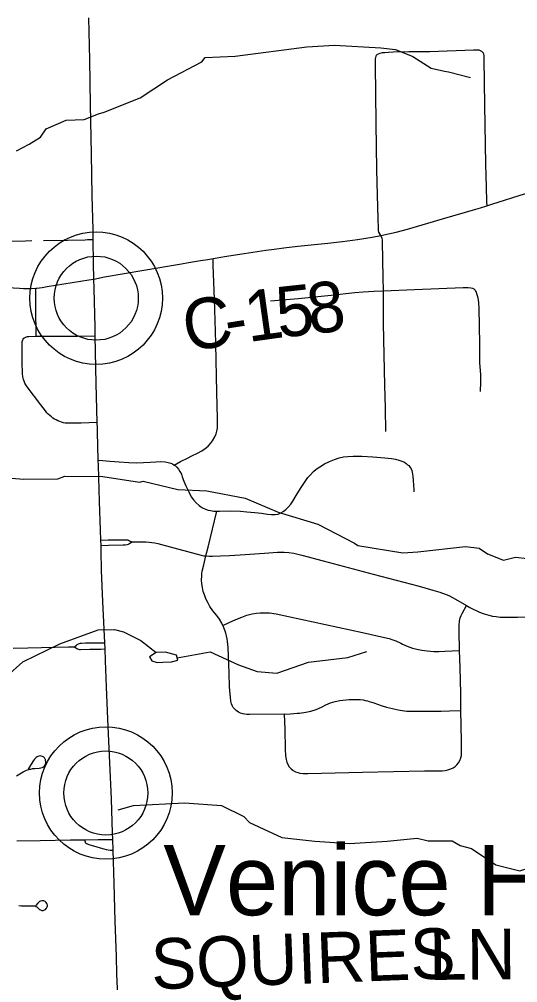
# Model space of a CAD drawing. Extents: x -6.4 to 34, y -4.2 to 22.
# Drawn here: x 5.367 to 5.927, y 19.085 to 20.167 of the extents above; entities that cross this region are included whole.
import ezdxf

# ---------------------------------------------------------------- set-up
doc = ezdxf.new("R2010")
doc.units = 0
for name, color, linetype in [('GM_X_County_Road', 7, 'Continuous'), ('GM_X_County_Road_Text', 7, 'Continuous'), ('GM_X_Minor_Lake', 7, 'Continuous'), ('GM_X_Minor_River', 7, 'Continuous'), ('GM_X_State_Route', 7, 'Continuous'), ('GM_X_Township_Road', 7, 'Continuous'), ('GM_X_Unincorporated', 7, 'Continuous'), ('GM_X_Unincorporated_Location', 7, 'Continuous'), ('GM_X_Unincorporated_Text', 7, 'Continuous')]:
    doc.layers.add(name, color=color, linetype=linetype)

msp = doc.modelspace()

# ---------------------------------------------------------------- linework, layer by layer
at = {"layer": 'GM_X_County_Road'}
msp.add_lwpolyline([(5.4509, 19.875), (5.4626, 19.8774), (5.5068, 19.8848), (5.5493, 19.8921), (5.5572, 19.8935), (5.5706, 19.8957), (5.5787, 19.897), (5.5847, 19.898), (5.5894, 19.8987), (5.5976, 19.9001), (5.6196, 19.9036), (5.6439, 19.9074), (5.6533, 19.9087), (5.6641, 19.9101), (5.6797, 19.912), (5.7134, 19.9153), (5.7302, 19.9173), (5.7468, 19.9193), (5.7633, 19.9221), (5.7731, 19.9239), (5.7816, 19.9257), (5.7902, 19.9277), (5.803, 19.9309), (5.8425, 19.9427), (5.8799, 19.9535), (5.8851, 19.955), (5.892, 19.9572), (5.8979, 19.959), (5.9357, 19.9709)], dxfattribs=at)
at = {"layer": 'GM_X_Minor_Lake'}
msp.add_line((5.5219, 19.4445), (5.5283, 19.4446), dxfattribs=at)
msp.add_lwpolyline([(5.5283, 19.4446), (5.5381, 19.4451), (5.5449, 19.4471), (5.5437, 19.4528), (5.5312, 19.456), (5.5206, 19.4555), (5.5134, 19.4508), (5.5158, 19.4463), (5.5219, 19.4445)], dxfattribs=at)
at = {"layer": 'GM_X_Minor_River'}
for points in [[(5.3637, 20.019), (5.378, 20.0265), (5.3907, 20.0343), (5.397, 20.0435), (5.4196, 20.0534), (5.44, 20.0541), (5.4558, 20.0604), (5.4623, 20.0624), (5.5029, 20.0783), (5.5333, 20.0985), (5.5719, 20.1189), (5.5756, 20.1236), (5.6093, 20.1253), (5.6898, 20.1357), (5.7212, 20.1374), (5.7732, 20.1345), (5.7895, 20.1328), (5.8089, 20.1248), (5.8296, 20.1119), (5.8448, 20.1083), (5.849, 20.1076), (5.8737, 20.1012)], [(5.3204, 19.6545), (5.372, 19.6501), (5.4102, 19.6507), (5.4181, 19.6535), (5.4609, 19.6534), (5.5019, 19.6469), (5.5061, 19.6481), (5.5452, 19.6385), (5.5778, 19.6372), (5.6208, 19.6288), (5.6578, 19.6131), (5.7023, 19.5998), (5.7435, 19.5784), (5.7474, 19.5758), (5.7979, 19.5676), (5.8145, 19.5686), (5.8682, 19.5748), (5.8834, 19.5728), (5.893, 19.5665), (5.9109, 19.5592), (5.9245, 19.5625), (5.9374, 19.5612)], [(5.2874, 19.3555), (5.2836, 19.3558), (5.2943, 19.3742), (5.3391, 19.411), (5.3528, 19.4287), (5.3711, 19.445), (5.4125, 19.4654), (5.4554, 19.481), (5.4739, 19.4816), (5.4842, 19.4788), (5.5037, 19.4692), (5.5206, 19.4555)], [(5.5444, 19.4497), (5.5815, 19.4565), (5.6132, 19.4418), (5.6341, 19.4342), (5.6561, 19.4323), (5.6919, 19.4447), (5.7362, 19.45), (5.7573, 19.4568)], [(5.478, 19.2789), (5.4953, 19.2838), (5.5524, 19.287), (5.5942, 19.2839), (5.6194, 19.2714), (5.6255, 19.2647), (5.6618, 19.2478), (5.699, 19.2439), (5.738, 19.2411), (5.7804, 19.2437), (5.814, 19.2473), (5.8262, 19.2441), (5.8531, 19.2442), (5.8623, 19.239), (5.8748, 19.2355), (5.9024, 19.2173), (5.9294, 19.2105), (5.9347, 19.2125), (5.9385, 19.2103), (5.9977, 19.2242), (6.0072, 19.2232), (6.0509, 19.2122)]]:
    msp.add_lwpolyline(points, dxfattribs=at)
at = {"layer": 'GM_X_State_Route'}
for points in [[(5.4547, 19.7077), (5.4545, 19.7139), (5.4534, 19.7577), (5.4523, 19.8113), (5.4521, 19.8208), (5.4512, 19.8645), (5.4509, 19.875), (5.4504, 19.8924), (5.45, 19.9193), (5.4498, 19.9305), (5.4489, 19.9683), (5.4481, 20.0156), (5.4471, 20.0706), (5.4462, 20.1213), (5.4452, 20.1683)], [(5.478, 19.0616), (5.4767, 19.0949), (5.4762, 19.1142), (5.4747, 19.1538), (5.4735, 19.1962), (5.4724, 19.2335), (5.472, 19.2458), (5.4718, 19.2527), (5.4704, 19.2914), (5.4687, 19.3316), (5.4666, 19.3806), (5.4651, 19.4172), (5.464, 19.4464), (5.4634, 19.4596), (5.4631, 19.4665), (5.4624, 19.4818), (5.4609, 19.513), (5.4595, 19.5476), (5.4591, 19.57), (5.4589, 19.5757), (5.4587, 19.5819), (5.4583, 19.5931), (5.4572, 19.6253), (5.4559, 19.6657), (5.4557, 19.6715), (5.4548, 19.7035), (5.4547, 19.7077)]]:
    msp.add_lwpolyline(points, dxfattribs=at)
at = {"layer": 'GM_X_Township_Road'}
for points in [[(5.7731, 19.9239), (5.7708, 19.9275), (5.7705, 19.9295), (5.7705, 19.9316), (5.77, 19.9431), (5.7693, 19.9693), (5.7686, 19.9981), (5.7679, 20.0495), (5.7675, 20.0837), (5.7672, 20.1147), (5.7671, 20.1205), (5.7672, 20.1223), (5.7674, 20.1239), (5.7678, 20.1254), (5.7683, 20.1263), (5.769, 20.127), (5.7705, 20.128), (5.7725, 20.1287), (5.7748, 20.1292), (5.7776, 20.1295), (5.7817, 20.1299), (5.787, 20.1302), (5.8045, 20.1306), (5.8281, 20.1306), (5.8772, 20.1323), (5.8809, 20.1324), (5.8832, 20.1322), (5.8848, 20.1317), (5.8863, 20.131), (5.887, 20.1302), (5.888, 20.1289), (5.8885, 20.1275), (5.8887, 20.1258), (5.8889, 20.122), (5.8896, 20.0701), (5.8905, 20.0041), (5.8913, 19.9783), (5.8919, 19.9621), (5.892, 19.9572)], [(5.3088, 19.877), (5.3104, 19.8826), (5.3134, 19.8926), (5.3158, 19.9003), (5.3175, 19.905), (5.3186, 19.9074), (5.3198, 19.9092), (5.3208, 19.9103), (5.3232, 19.9123), (5.3263, 19.9144), (5.3296, 19.916), (5.3317, 19.9167), (5.3339, 19.9172), (5.3361, 19.9174), (5.3389, 19.9174), (5.374, 19.918), (5.381, 19.9181)], [(5.3943, 19.9184), (5.4213, 19.9188), (5.4411, 19.9191), (5.4436, 19.9192), (5.45, 19.9193)], [(5.7786, 19.7039), (5.7783, 19.73), (5.7777, 19.7557), (5.7767, 19.7899), (5.7762, 19.8251), (5.7761, 19.8617), (5.7759, 19.8766), (5.7751, 19.9169), (5.775, 19.9191), (5.7747, 19.9206), (5.7731, 19.9239)], [(5.5411, 19.6661), (5.5482, 19.67), (5.5558, 19.674), (5.5608, 19.6764), (5.567, 19.6793), (5.5719, 19.6821), (5.5756, 19.6846), (5.579, 19.6875), (5.5817, 19.6902), (5.5839, 19.6933), (5.5865, 19.6977), (5.588, 19.7012), (5.5889, 19.7043), (5.5895, 19.7075), (5.5896, 19.7119), (5.5895, 19.7184), (5.5888, 19.7474), (5.5876, 19.8021), (5.5873, 19.8164), (5.5862, 19.8525), (5.5849, 19.8904), (5.5847, 19.898)], [(5.3088, 19.877), (5.3156, 19.8753), (5.3237, 19.8729), (5.3303, 19.8709), (5.338, 19.8689), (5.3483, 19.8667), (5.3605, 19.865), (5.3673, 19.8646), (5.3716, 19.8645), (5.3759, 19.8644), (5.3803, 19.8645), (5.3854, 19.8648), (5.3867, 19.8649), (5.3925, 19.8655), (5.3983, 19.8665), (5.445, 19.874), (5.4509, 19.875)], [(5.3858, 19.8107), (5.3854, 19.8424), (5.3854, 19.8605), (5.3854, 19.8648)], [(5.6493, 19.8506), (5.6803, 19.8531), (5.7174, 19.8569), (5.7438, 19.8597), (5.7532, 19.8606), (5.7651, 19.8613), (5.7761, 19.8617), (5.8111, 19.8632), (5.8655, 19.8656), (5.8711, 19.8656)], [(5.8711, 19.8656), (5.8742, 19.8652), (5.876, 19.8647), (5.8774, 19.864), (5.8782, 19.8632), (5.8789, 19.8623), (5.8795, 19.8615), (5.8801, 19.8602), (5.8807, 19.8587), (5.8815, 19.8564), (5.882, 19.854), (5.8824, 19.8515), (5.8828, 19.8482), (5.8832, 19.8423), (5.8837, 19.8224), (5.8839, 19.8019), (5.8838, 19.7948), (5.8841, 19.7812), (5.8849, 19.7673), (5.8849, 19.7596), (5.8846, 19.7487)], [(5.4545, 19.7139), (5.4364, 19.7133), (5.4239, 19.713), (5.4213, 19.7131), (5.4187, 19.7133), (5.4165, 19.7137), (5.4144, 19.7143), (5.4124, 19.7149), (5.4103, 19.7157), (5.4084, 19.7167), (5.4065, 19.7178), (5.4047, 19.7189), (5.4031, 19.7202), (5.4014, 19.7217), (5.3996, 19.7233), (5.398, 19.7249), (5.3963, 19.727), (5.3912, 19.7338), (5.3758, 19.7541), (5.3744, 19.7562), (5.3733, 19.7582), (5.3724, 19.7602), (5.3718, 19.7621), (5.3713, 19.7638), (5.371, 19.7656), (5.3707, 19.7686), (5.3704, 19.782), (5.3701, 19.7972), (5.3701, 19.8003), (5.3702, 19.8027), (5.3704, 19.8043), (5.3706, 19.8056), (5.371, 19.8067), (5.3715, 19.8076), (5.3721, 19.8084), (5.3728, 19.8091), (5.3739, 19.8098), (5.3751, 19.8102), (5.3763, 19.8104), (5.3776, 19.8105), (5.3858, 19.8107), (5.4324, 19.811), (5.4523, 19.8113)], [(5.4557, 19.6715), (5.4606, 19.6711), (5.4687, 19.6704), (5.4793, 19.6696), (5.4901, 19.6689), (5.4989, 19.6685), (5.5064, 19.6689), (5.5139, 19.6695), (5.5203, 19.6699), (5.5258, 19.67), (5.5307, 19.6698), (5.5342, 19.6691), (5.5371, 19.6683), (5.5392, 19.6673), (5.5411, 19.6661), (5.5423, 19.6653), (5.5439, 19.6637), (5.5459, 19.6614), (5.5475, 19.6589), (5.5491, 19.6557), (5.5501, 19.6529), (5.5518, 19.6482), (5.5539, 19.6429), (5.5573, 19.636), (5.5602, 19.6306), (5.5628, 19.6269), (5.5658, 19.6236), (5.5692, 19.6207), (5.5707, 19.6195), (5.5728, 19.6181), (5.5763, 19.6164), (5.5793, 19.6154), (5.5819, 19.6149), (5.5857, 19.6145), (5.5889, 19.6145), (5.592, 19.6145), (5.6044, 19.6148), (5.6156, 19.6144), (5.6225, 19.6137), (5.6317, 19.6127), (5.6391, 19.6119), (5.6459, 19.611), (5.6504, 19.6106), (5.6545, 19.6106), (5.6576, 19.6111), (5.6606, 19.6123), (5.6634, 19.6139), (5.6665, 19.6162), (5.6692, 19.6188), (5.6721, 19.6223), (5.6742, 19.6254), (5.678, 19.6319), (5.6827, 19.6399), (5.6872, 19.6466), (5.6912, 19.652), (5.6936, 19.6548), (5.6974, 19.6587), (5.7006, 19.6614), (5.7046, 19.6642), (5.7099, 19.6673), (5.7154, 19.67), (5.721, 19.6724), (5.7263, 19.6741), (5.731, 19.6752), (5.7359, 19.6758), (5.742, 19.6761), (5.7519, 19.676), (5.7643, 19.6753), (5.7776, 19.6742), (5.7851, 19.6734), (5.7894, 19.6727), (5.7932, 19.6717), (5.7967, 19.6706), (5.7997, 19.6693), (5.8016, 19.6677), (5.8031, 19.6665), (5.8044, 19.6655), (5.8052, 19.6645), (5.8061, 19.6634), (5.807, 19.6618), (5.8078, 19.6601), (5.8084, 19.658), (5.8091, 19.6536), (5.8095, 19.6487), (5.8102, 19.6383), (5.8103, 19.6359)], [(5.6645, 19.3865), (5.6254, 19.386), (5.6226, 19.386), (5.618, 19.3866), (5.6155, 19.3874), (5.6132, 19.3886), (5.6106, 19.3904), (5.6087, 19.3922), (5.6074, 19.3938), (5.6064, 19.3955), (5.6054, 19.3979), (5.6047, 19.4011), (5.6042, 19.4055), (5.6037, 19.4089), (5.6031, 19.4172), (5.6027, 19.4329), (5.6015, 19.4612), (5.6009, 19.4679), (5.6005, 19.4709), (5.5998, 19.4745), (5.599, 19.4772), (5.5983, 19.4797), (5.5965, 19.4843), (5.5957, 19.4859), (5.5944, 19.4887), (5.5919, 19.4929), (5.5888, 19.4972), (5.5865, 19.4999), (5.5843, 19.5026), (5.5811, 19.5073), (5.5786, 19.5117), (5.5766, 19.5158), (5.5749, 19.5202), (5.5737, 19.5243), (5.5726, 19.5286), (5.5721, 19.5326), (5.5718, 19.5371), (5.5719, 19.5413), (5.572, 19.5441), (5.5725, 19.5469), (5.5741, 19.5541), (5.5766, 19.564), (5.5793, 19.574), (5.5889, 19.6145)], [(5.4587, 19.5819), (5.4668, 19.5821), (5.4775, 19.5822), (5.4853, 19.5823), (5.4869, 19.5822), (5.4884, 19.582), (5.4897, 19.5816)], [(5.4897, 19.5816), (5.4909, 19.5811), (5.4934, 19.5799)], [(5.4589, 19.5757), (5.4672, 19.576), (5.4837, 19.5765), (5.486, 19.5766), (5.4883, 19.5769), (5.4895, 19.5772), (5.4902, 19.5775)], [(5.4902, 19.5775), (5.4909, 19.5779), (5.4934, 19.5799)], [(5.4934, 19.5799), (5.5035, 19.5799), (5.5065, 19.5799), (5.5096, 19.5798), (5.5127, 19.5796), (5.5157, 19.5792), (5.5191, 19.5786), (5.5225, 19.578), (5.5405, 19.5733), (5.5712, 19.565), (5.5743, 19.5643), (5.5766, 19.564), (5.5803, 19.5638), (5.584, 19.5637), (5.5931, 19.564), (5.6032, 19.5645), (5.615, 19.5654), (5.6423, 19.5673), (5.6572, 19.5683), (5.6647, 19.5684), (5.6697, 19.5681), (5.6753, 19.5672), (5.6844, 19.565), (5.7085, 19.5587), (5.7646, 19.5437), (5.8162, 19.5301), (5.8317, 19.5257), (5.8395, 19.5234), (5.8465, 19.5207), (5.8494, 19.5195), (5.8545, 19.517), (5.8692, 19.5083), (5.8732, 19.5062), (5.8838, 19.5011), (5.889, 19.4991), (5.8944, 19.4974), (5.8986, 19.4965), (5.9026, 19.4959), (5.9072, 19.4954), (5.912, 19.4952), (5.9268, 19.4954), (5.9604, 19.4958)], [(5.6645, 19.3865), (5.6651, 19.3694), (5.6657, 19.347), (5.6661, 19.3396), (5.6667, 19.3354), (5.6674, 19.3325), (5.6686, 19.3298), (5.6702, 19.3273), (5.6722, 19.3251), (5.6745, 19.3233), (5.6771, 19.3218), (5.6799, 19.3207), (5.6821, 19.3202), (5.6857, 19.3198), (5.6912, 19.3198), (5.7527, 19.3211), (5.822, 19.3226), (5.8326, 19.3227), (5.8369, 19.3228), (5.8419, 19.3229), (5.8455, 19.3231), (5.8484, 19.3237), (5.8518, 19.3249), (5.8545, 19.3262), (5.8565, 19.3275), (5.8586, 19.3295), (5.8604, 19.3318), (5.8619, 19.3344), (5.8629, 19.3372), (5.8636, 19.3401), (5.8639, 19.3437), (5.8639, 19.3455), (5.8637, 19.3566), (5.8631, 19.3906), (5.8628, 19.4096), (5.8622, 19.4388), (5.8616, 19.458), (5.8611, 19.4801), (5.861, 19.4863), (5.8615, 19.4908), (5.8623, 19.4945), (5.8634, 19.4973), (5.8645, 19.4996), (5.8692, 19.5083)], [(5.5957, 19.4859), (5.6028, 19.4892), (5.6101, 19.4926), (5.6169, 19.4954), (5.6227, 19.4974), (5.6287, 19.4989), (5.6335, 19.4997), (5.6377, 19.5001), (5.6432, 19.5003), (5.6481, 19.5001), (5.6554, 19.4991), (5.7526, 19.4781), (5.7774, 19.4726), (5.7823, 19.4714), (5.7865, 19.47), (5.7899, 19.4688), (5.7954, 19.4662), (5.7976, 19.4651), (5.8028, 19.4627), (5.8086, 19.4606), (5.8135, 19.4594), (5.819, 19.4584), (5.8252, 19.4575), (5.8327, 19.4569), (5.8383, 19.4569), (5.8451, 19.4572), (5.8532, 19.4576), (5.8616, 19.458)], [(5.4291, 19.462), (5.4311, 19.464), (5.432, 19.4646), (5.4326, 19.4649), (5.4336, 19.4654), (5.4346, 19.4657), (5.4358, 19.466), (5.437, 19.4661), (5.4414, 19.4663), (5.4457, 19.4664), (5.4581, 19.4665), (5.4631, 19.4665)], [(5.3602, 19.4606), (5.3765, 19.4608), (5.4222, 19.4619)], [(5.4222, 19.4619), (5.4291, 19.462), (5.4305, 19.4608), (5.4315, 19.4601), (5.4325, 19.4596), (5.4335, 19.4593), (5.4346, 19.4591), (5.4358, 19.459), (5.4461, 19.4593), (5.4587, 19.4595), (5.4634, 19.4596)], [(5.6645, 19.3865), (5.6715, 19.3869), (5.6792, 19.3874), (5.6816, 19.3876), (5.6889, 19.3886), (5.6944, 19.3897), (5.7003, 19.3916), (5.7032, 19.3928), (5.7071, 19.3947), (5.7115, 19.3969), (5.7166, 19.399), (5.7219, 19.4006), (5.7272, 19.4016), (5.7306, 19.4022), (5.7343, 19.4026), (5.7375, 19.4028), (5.7406, 19.403), (5.744, 19.403), (5.7466, 19.4029), (5.7498, 19.4027), (5.7531, 19.4023), (5.7555, 19.4019), (5.758, 19.4014), (5.7601, 19.4007), (5.7653, 19.399), (5.7736, 19.3962), (5.7796, 19.3943), (5.7863, 19.3927), (5.7927, 19.3912), (5.7971, 19.3905), (5.8025, 19.3899), (5.8076, 19.3896), (5.8158, 19.3896), (5.8308, 19.3896), (5.8408, 19.3898), (5.8501, 19.3901), (5.8631, 19.3906)], [(5.3639, 19.3173), (5.3712, 19.3217), (5.3729, 19.3225), (5.3745, 19.3232), (5.3763, 19.3239), (5.3776, 19.3243), (5.3787, 19.3245), (5.3799, 19.3247), (5.382, 19.3252), (5.3845, 19.3255), (5.3894, 19.3259), (5.3911, 19.3261), (5.3925, 19.3264), (5.3935, 19.3269), (5.3944, 19.3275), (5.3952, 19.3282), (5.3958, 19.329), (5.3962, 19.3298), (5.3966, 19.3307), (5.3967, 19.3315), (5.3968, 19.3324), (5.3968, 19.3333), (5.3966, 19.3344), (5.3964, 19.3353), (5.3961, 19.336), (5.3953, 19.3372), (5.3946, 19.338), (5.3938, 19.3385), (5.3929, 19.339), (5.3917, 19.3394), (5.3906, 19.3395), (5.3891, 19.3393), (5.388, 19.339), (5.3869, 19.3385), (5.3858, 19.3377), (5.3842, 19.3359), (5.3831, 19.3345), (5.3823, 19.3334), (5.3792, 19.3284), (5.3771, 19.3247)], [(5.3642, 19.2442), (5.3903, 19.2447), (5.4244, 19.2452), (5.4402, 19.2453), (5.4556, 19.2455), (5.4696, 19.2458), (5.472, 19.2458)], [(5.4402, 19.2453), (5.4405, 19.2443), (5.4408, 19.2431), (5.4411, 19.2424), (5.4417, 19.2417), (5.4423, 19.2412), (5.4428, 19.2409), (5.4436, 19.2406), (5.445, 19.2401), (5.4488, 19.239), (5.453, 19.2378), (5.4578, 19.2364), (5.4618, 19.2352), (5.4646, 19.2345), (5.4669, 19.234), (5.4689, 19.2337), (5.4724, 19.2335)], [(5.3666, 19.1714), (5.369, 19.1712), (5.3737, 19.1711), (5.379, 19.1713), (5.3828, 19.1713), (5.3839, 19.1712), (5.3847, 19.171), (5.3858, 19.1706), (5.3866, 19.1701), (5.3876, 19.1693), (5.3882, 19.1686), (5.3887, 19.1682), (5.3898, 19.1672), (5.3909, 19.1665), (5.3916, 19.1662), (5.3922, 19.1661), (5.3931, 19.1661), (5.3939, 19.1661), (5.3947, 19.1663), (5.3953, 19.1665), (5.3959, 19.1669), (5.3965, 19.1672), (5.3973, 19.1681), (5.3977, 19.1687), (5.3981, 19.1693), (5.3983, 19.1701), (5.3985, 19.1711), (5.3985, 19.1719), (5.3984, 19.1727), (5.3981, 19.1737), (5.3973, 19.1749), (5.3969, 19.1754), (5.3962, 19.176), (5.3954, 19.1765), (5.3944, 19.1768), (5.3937, 19.1769), (5.3922, 19.1769), (5.3909, 19.1765), (5.3897, 19.1759), (5.3889, 19.1752), (5.3879, 19.1742), (5.3854, 19.1714)]]:
    msp.add_lwpolyline(points, dxfattribs=at)
at = {"layer": 'GM_X_Unincorporated'}
for centre, radius in [((5.4534, 19.8535), 0.0744), ((5.4534, 19.8535), 0.0472), ((5.4642, 19.2979), 0.0744), ((5.4642, 19.2979), 0.0472)]:
    msp.add_circle(centre, radius, dxfattribs=at)
at = {"layer": 'GM_X_Unincorporated_Location'}
for p, q in [((5.4534, 19.8535), (5.4534, 19.8535)), ((5.4642, 19.2979), (5.4642, 19.2979))]:
    msp.add_line(p, q, dxfattribs=at)

# ---------------------------------------------------------------- texts
at = {"layer": 'GM_X_County_Road_Text'}
for s, height, rotation, p in [('1', 0.0568, 7.9641, (5.6242, 19.8041)), ('5', 0.0568, 6.2258, (5.6584, 19.8089)), ('8', 0.0568, 6.7386, (5.6937, 19.8128)), ('C', 0.0568, 9.1704, (5.5554, 19.7932)), ('-', 0.0568, 8.8322, (5.6013, 19.8006)), ('SQUIRES', 0.05682, 2.1444, (5.516, 19.0773)), ('LN', 0.05682, 0.5159, (5.8276, 19.0879))]:
    msp.add_text(s, height=height, rotation=rotation, dxfattribs=at).set_placement(p)
at = {"layer": 'GM_X_Unincorporated_Text'}
msp.add_text('Venice Heights', height=0.078977, rotation=0, dxfattribs=at).set_placement((5.5287, 19.1606))

doc.saveas('drawing.dxf')
